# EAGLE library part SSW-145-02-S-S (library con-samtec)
THROUGH-HOLE .025" SQ POST SOCKET Source: Samtec SSW.pdf
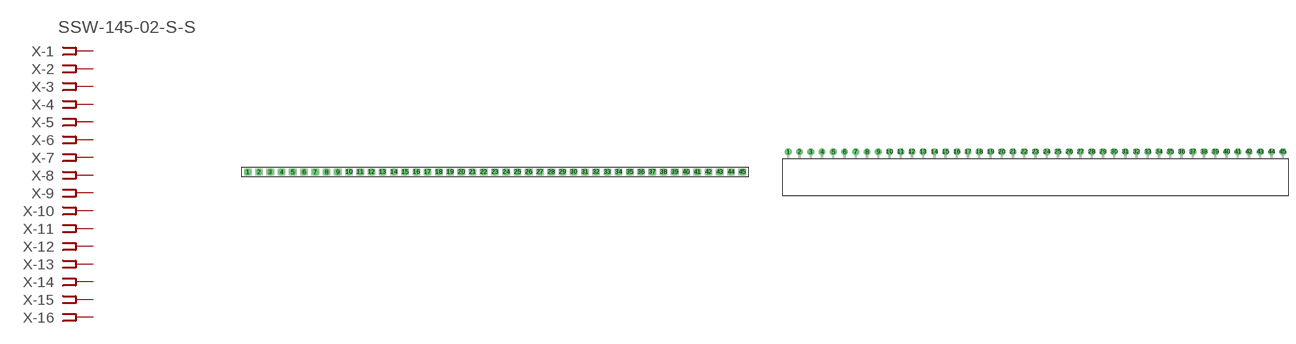
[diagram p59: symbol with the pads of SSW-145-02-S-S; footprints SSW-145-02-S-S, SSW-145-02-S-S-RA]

Designator prefix X; gates -1=FPINV -2=FPIN -3=FPIN -4=FPIN -5=FPIN -6=FPIN -7=FPIN -8=FPIN -9=FPIN -10=FPIN -11=FPIN -12=FPIN -13=FPIN -14=FPIN -15=FPIN -16=FPIN -17=FPIN -18=FPIN -19=FPIN -20=FPIN -21=FPIN -22=FPIN -23=FPIN -24=FPIN -25=FPIN -26=FPIN -27=FPIN -28=FPIN -29=FPIN -30=FPIN -31=FPIN -32=FPIN -33=FPIN -34=FPIN -35=FPIN -36=FPIN -37=FPIN -38=FPIN -39=FPIN -40=FPIN -41=FPIN -42=FPIN -43=FPIN -44=FPIN -45=FPIN

## SSW-145-02-S-S (OC_FARNELL: unknown; OC_NEWARK: unknown)  [SSW-145-02-S-S]
1  -1:1  pas
2  -2:1  pas
3  -3:1  pas
4  -4:1  pas
5  -5:1  pas
6  -6:1  pas
7  -7:1  pas
8  -8:1  pas
9  -9:1  pas
10  -10:1  pas
11  -11:1  pas
12  -12:1  pas
13  -13:1  pas
14  -14:1  pas
15  -15:1  pas
16  -16:1  pas
17  -17:1  pas
18  -18:1  pas
19  -19:1  pas
20  -20:1  pas
21  -21:1  pas
22  -22:1  pas
23  -23:1  pas
24  -24:1  pas
25  -25:1  pas
26  -26:1  pas
27  -27:1  pas
28  -28:1  pas
29  -29:1  pas
30  -30:1  pas
31  -31:1  pas
32  -32:1  pas
33  -33:1  pas
34  -34:1  pas
35  -35:1  pas
36  -36:1  pas
37  -37:1  pas
38  -38:1  pas
39  -39:1  pas
40  -40:1  pas
41  -41:1  pas
42  -42:1  pas
43  -43:1  pas
44  -44:1  pas
45  -45:1  pas

## SSW-145-02-S-S-RA (OC_FARNELL: unknown; OC_NEWARK: unknown)  [SSW-145-02-S-S-RA]
Pads as for SSW-145-02-S-S

## Footprint SSW-145-02-S-S (pad centres in mm)
THROUGH-HOLE .025" SQ POST SOCKET Source: Samtec SSW.pdf
drill 1 pad 1.5 octagon: 1 -55.88,0; 2 -53.34,0; 3 -50.8,0; 4 -48.26,0; 5 -45.72,0; 6 -43.18,0; 7 -40.64,0; 8 -38.1,0; 9 -35.56,0; 10 -33.02,0; 11 -30.48,0; 12 -27.94,0; 13 -25.4,0; 14 -22.86,0; 15 -20.32,0; 16 -17.78,0; 17 -15.24,0; 18 -12.7,0; 19 -10.16,0; 20 -7.62,0; 21 -5.08,0; 22 -2.54,0; 23 0,0; 24 2.54,0; 25 5.08,0; 26 7.62,0; 27 10.16,0; 28 12.7,0; 29 15.24,0; 30 17.78,0; 31 20.32,0; 32 22.86,0; 33 25.4,0; 34 27.94,0; 35 30.48,0; 36 33.02,0; 37 35.56,0; 38 38.1,0; 39 40.64,0; 40 43.18,0; 41 45.72,0; 42 48.26,0; 43 50.8,0; 44 53.34,0; 45 55.88,0

## Footprint SSW-145-02-S-S-RA (pad centres in mm)
THROUGH-HOLE .025" SQ POST SOCKET Source: Samtec SSW.pdf
drill 1 pad 1.5 octagon: 1 -55.88,1.524; 2 -53.34,1.524; 3 -50.8,1.524; 4 -48.26,1.524; 5 -45.72,1.524; 6 -43.18,1.524; 7 -40.64,1.524; 8 -38.1,1.524; 9 -35.56,1.524; 10 -33.02,1.524; 11 -30.48,1.524; 12 -27.94,1.524; 13 -25.4,1.524; 14 -22.86,1.524; 15 -20.32,1.524; 16 -17.78,1.524; 17 -15.24,1.524; 18 -12.7,1.524; 19 -10.16,1.524; 20 -7.62,1.524; 21 -5.08,1.524; 22 -2.54,1.524; 23 0,1.524; 24 2.54,1.524; 25 5.08,1.524; 26 7.62,1.524; 27 10.16,1.524; 28 12.7,1.524; 29 15.24,1.524; 30 17.78,1.524; 31 20.32,1.524; 32 22.86,1.524; 33 25.4,1.524; 34 27.94,1.524; 35 30.48,1.524; 36 33.02,1.524; 37 35.56,1.524; 38 38.1,1.524; 39 40.64,1.524; 40 43.18,1.524; 41 45.72,1.524; 42 48.26,1.524; 43 50.8,1.524; 44 53.34,1.524; 45 55.88,1.524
